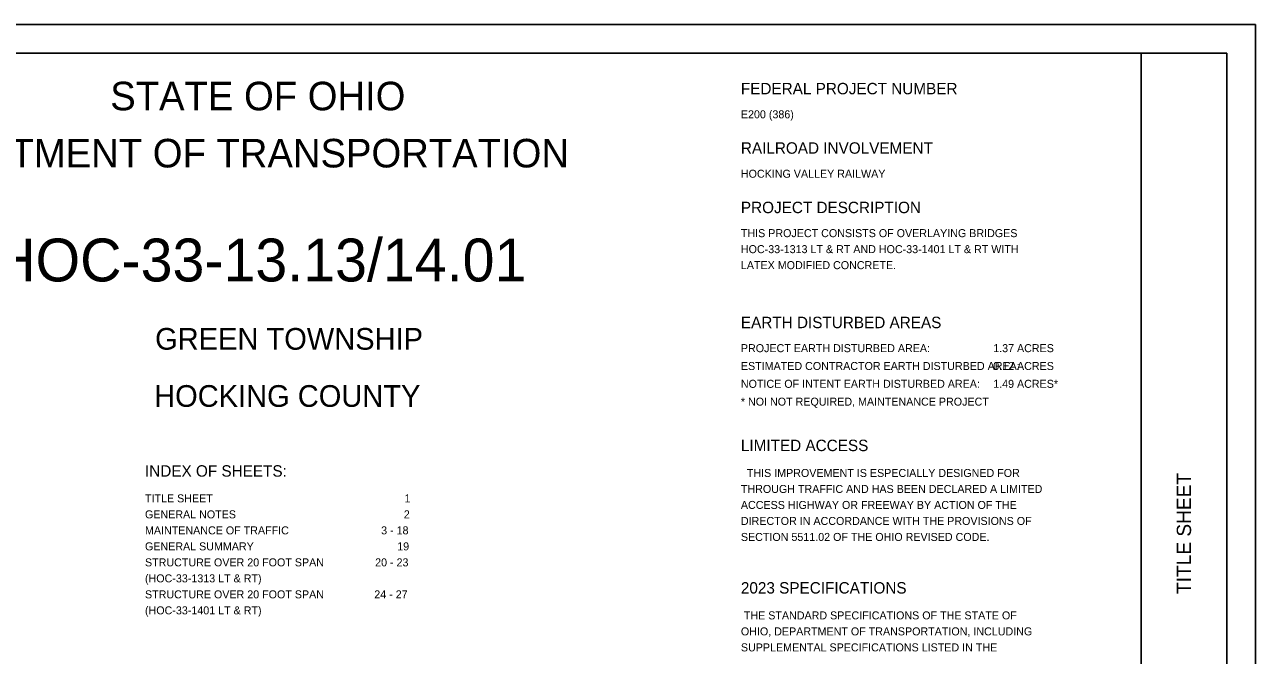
# Model space of a CAD drawing. Extents: x 39.8 to 73.8, y 13 to 35.
# Drawn here: x 52.23 to 73.76, y 23.92 to 34.96 of the extents above; entities that cross this region are included whole.
import ezdxf

# ---------------------------------------------------------------- set-up
doc = ezdxf.new("R2010")
doc.units = 0
for name, color, linetype in [('SH_Border', 7, 'Continuous'), ('SH_Cut_Line', 7, 'Continuous'), ('SH_Data', 7, 'Continuous'), ('SH_Text', 7, 'Continuous')]:
    doc.layers.add(name, color=color, linetype=linetype)

msp = doc.modelspace()

# ---------------------------------------------------------------- linework, layer by layer
at = {"layer": 'SH_Border'}
msp.add_line((71.763, 13.465), (71.763, 34.465), dxfattribs=at)
msp.add_lwpolyline([(41.263, 34.465), (73.263, 34.465), (73.263, 13.465), (41.263, 13.465)], close=True, dxfattribs=at)
at = {"layer": 'SH_Cut_Line'}
msp.add_lwpolyline([(39.763, 12.965), (73.763, 12.965), (73.763, 34.965), (39.763, 34.965)], close=True, dxfattribs=at)

# ---------------------------------------------------------------- texts
at = {"layer": 'SH_Data'}
msp.add_text('TITLE SHEET', height=0.25, rotation=90, dxfattribs=at).set_placement((72.638, 25))
at = {"layer": 'SH_Text'}
for s, height, p in [('STATE OF OHIO', 0.5, (53.731, 33.465)), ('FEDERAL PROJECT NUMBER', 0.2, (64.763, 33.745)), ('E200 (386)', 0.14, (64.763, 33.325)), ('DEPARTMENT OF TRANSPORTATION', 0.5, (49.683, 32.465)), ('RAILROAD INVOLVEMENT', 0.2, (64.763, 32.705)), ('HOCKING VALLEY RAILWAY', 0.14, (64.763, 32.285)), ('PROJECT DESCRIPTION', 0.2, (64.763, 31.665)), ('HOC-33-13.13/14.01', 0.75, (51.7, 30.47)), ('THIS PROJECT CONSISTS OF OVERLAYING BRIDGES', 0.14, (64.763, 31.245)), ('HOC-33-1313 LT & RT AND HOC-33-1401 LT & RT WITH', 0.14, (64.763, 30.965)), ('LATEX MODIFIED CONCRETE.', 0.14, (64.763, 30.685)), ('EARTH DISTURBED AREAS', 0.2, (64.763, 29.652)), ('GREEN TOWNSHIP', 0.38, (54.516, 29.275)), ('PROJECT EARTH DISTURBED AREA:', 0.14, (64.763, 29.232)), ('1.37 ACRES', 0.14, (69.177, 29.232)), ('ESTIMATED CONTRACTOR EARTH DISTURBED AREA:', 0.14, (64.763, 28.92)), ('0.12 ACRES', 0.14, (69.177, 28.92)), ('HOCKING COUNTY', 0.38, (54.499, 28.275)), ('NOTICE OF INTENT EARTH DISTURBED AREA:', 0.14, (64.763, 28.608)), ('1.49 ACRES*', 0.14, (69.177, 28.608)), ('* NOI NOT REQUIRED, MAINTENANCE PROJECT', 0.14, (64.763, 28.296)), ('LIMITED ACCESS', 0.2, (64.763, 27.5)), ('INDEX OF SHEETS:', 0.2, (54.339, 27.053)), ('  THIS IMPROVEMENT IS ESPECIALLY DESIGNED FOR', 0.14, (64.763, 27.048)), ('TITLE SHEET', 0.14, (54.339, 26.603)), ('1', 0.14, (58.879, 26.603)), ('THROUGH TRAFFIC AND HAS BEEN DECLARED A LIMITED', 0.14, (64.763, 26.768)), ('ACCESS HIGHWAY OR FREEWAY BY ACTION OF THE', 0.14, (64.763, 26.488)), ('GENERAL NOTES', 0.14, (54.339, 26.323)), ('2', 0.14, (58.867, 26.323)), ('DIRECTOR IN ACCORDANCE WITH THE PROVISIONS OF', 0.14, (64.763, 26.208)), ('MAINTENANCE OF TRAFFIC', 0.14, (54.339, 26.043)), ('3 - 18', 0.14, (58.47, 26.043)), ('SECTION 5511.02 OF THE OHIO REVISED CODE.', 0.14, (64.763, 25.928)), ('GENERAL SUMMARY', 0.14, (54.339, 25.763)), ('19', 0.14, (58.751, 25.763)), ('STRUCTURE OVER 20 FOOT SPAN', 0.14, (54.339, 25.483)), ('20 - 23', 0.14, (58.365, 25.483)), ('(HOC-33-1313 LT & RT)', 0.14, (54.339, 25.203)), ('2023 SPECIFICATIONS', 0.2, (64.763, 25.007)), ('STRUCTURE OVER 20 FOOT SPAN', 0.14, (54.339, 24.923)), ('24 - 27', 0.14, (58.35, 24.923)), ('(HOC-33-1401 LT & RT)', 0.14, (54.339, 24.643)), (' THE STANDARD SPECIFICATIONS OF THE STATE OF', 0.14, (64.763, 24.555)), ('OHIO, DEPARTMENT OF TRANSPORTATION, INCLUDING', 0.14, (64.763, 24.275)), ('SUPPLEMENTAL SPECIFICATIONS LISTED IN THE', 0.14, (64.763, 23.995))]:
    msp.add_text(s, height=height, dxfattribs=at).set_placement(p)

doc.saveas('drawing.dxf')
